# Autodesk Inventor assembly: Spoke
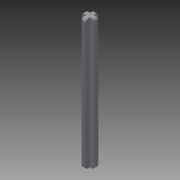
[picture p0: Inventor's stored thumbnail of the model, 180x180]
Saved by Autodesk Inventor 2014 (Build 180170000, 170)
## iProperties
Created: 2014-06
Part Number: Spoke
Document SubType Name: Assembly
Designer: Aser
Author: Aser
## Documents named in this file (2)
- C:\Users\Aser\Documents\Spoke.iam
- C:\Users\Aser\Documents\Spoke_Part.ipt
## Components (2 placed, 1 different names)
1. Spoke_Part:1 — Mate:1, Mate:2, Mate:3
2. Spoke_Part:2 — Mate:1, Mate:2, Mate:3
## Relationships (3: Mate 3)
- Mate:1: Spoke_Part:1 ↔ Spoke_Part:2
- Mate:2: Spoke_Part:1 ↔ Spoke_Part:2
- Mate:3: Spoke_Part:1 ↔ Spoke_Part:2
